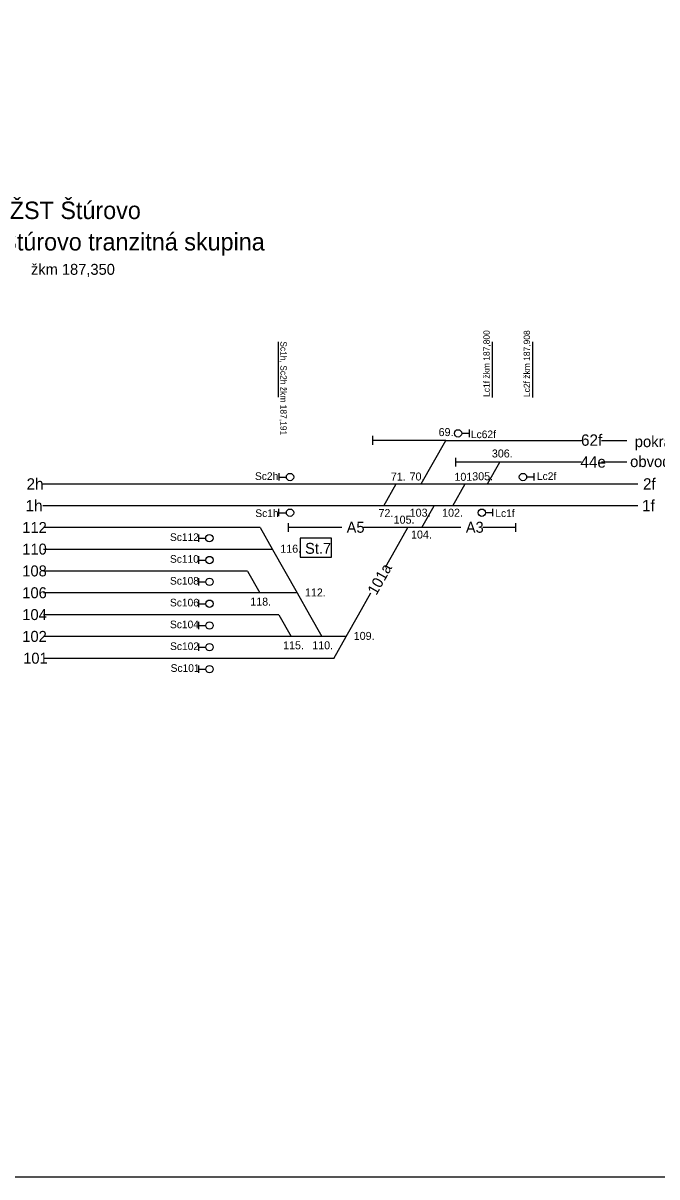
# Model space of a CAD drawing. Extents: x -119 to 851, y -238 to 59.
# Drawn here: x 499.2 to 557.3, y -238 to -132.3 of the extents above; entities that cross this region are included whole.
import ezdxf

# ---------------------------------------------------------------- set-up
doc = ezdxf.new("R2010")
doc.units = 0
for name, color, linetype in [('budova', 7, 'Continuous'), ('Level 2', 7, 'Continuous'), ('netlač', 7, 'Continuous'), ('popisky navestidla', 7, 'Continuous'), ('popisky stanic a zastavok', 7, 'Continuous'), ('PU_navestidla', 7, 'Continuous'), ('PU_oznacenie navestidiel', 7, 'Continuous'), ('PU_stan_kolaje', 7, 'Continuous'), ('PU_vlecky', 7, 'Continuous')]:
    doc.layers.add(name, color=color, linetype=linetype)

msp = doc.modelspace()

# ---------------------------------------------------------------- linework, layer by layer
at = {"layer": 'budova'}
msp.add_lwpolyline([(524.58, -181.22), (527.45, -181.22), (527.45, -179.47), (524.58, -179.47)], close=True, dxfattribs=at)
at = {"layer": 'Level 2'}
for p, q in [((531.26, -170.9), (531.26, -170.1)), ((537.94, -170.5), (531.26, -170.5)), ((538.86, -172.89), (538.86, -172.09)), ((538.96, -172.49), (538.86, -172.49)), ((543.3, -172.5), (538.9, -172.5)), ((550.36, -172.49), (542.88, -172.49)), ((554.52, -172.49), (552.2, -172.49)), ((523.53, -178.89), (523.53, -178.09)), ((528.41, -178.49), (523.53, -178.49)), ((534.45, -178.49), (530.41, -178.49)), ((539.32, -178.49), (535.73, -178.49)), ((544.36, -178.49), (541.32, -178.49)), ((544.36, -178.89), (544.36, -178.09))]:
    msp.add_line(p, q, dxfattribs=at)
at = {"layer": 'netlač'}
for p, q in [((537.94, -170.5), (550.36, -170.5)), ((552.2, -170.5), (554.52, -170.5)), ((501, -174.49), (555.55, -174.49)), ((555.55, -176.49), (501, -176.49)), ((520.94, -178.49), (501.07, -178.49)), ((535.73, -178.49), (534.45, -178.49)), ((522.07, -180.49), (501.07, -180.49)), ((519.77, -182.49), (501.07, -182.49)), ((524.33, -184.49), (501.07, -184.49)), ((522.64, -186.49), (501.07, -186.49)), ((528.8, -188.48), (501.07, -188.48)), ((527.67, -190.48), (501.07, -190.48))]:
    msp.add_line(p, q, dxfattribs=at)
at = {"layer": 'popisky navestidla'}
for p, q in [((522.62, -166.55), (522.62, -161.46)), ((542.2, -161.48), (542.2, -166.57)), ((545.88, -161.48), (545.88, -166.57))]:
    msp.add_line(p, q, dxfattribs=at)
msp.add_lwpolyline([(-118.95, -238.01), (851.05, -238.01), (851.05, 58.99), (-118.95, 58.99)], close=True, dxfattribs=at)
at = {"layer": 'PU_navestidla'}
for p, q in [((540.07, -169.86), (539.4, -169.86)), ((540.07, -169.52), (540.07, -170.2)), ((522.65, -173.52), (522.65, -174.19)), ((522.65, -173.86), (523.32, -173.86)), ((546.02, -173.86), (545.34, -173.86)), ((546.02, -173.52), (546.02, -174.19)), ((522.65, -177.46), (522.65, -176.79)), ((522.65, -177.13), (523.32, -177.13)), ((542.24, -177.13), (541.57, -177.13)), ((542.24, -177.46), (542.24, -176.79)), ((515.26, -179.14), (515.26, -179.81)), ((515.26, -179.47), (515.93, -179.47)), ((515.27, -181.13), (515.27, -181.81)), ((515.27, -181.47), (515.94, -181.47)), ((515.27, -183.13), (515.27, -183.8)), ((515.27, -183.47), (515.94, -183.47)), ((515.27, -185.13), (515.27, -185.8)), ((515.27, -185.47), (515.94, -185.47)), ((515.27, -187.13), (515.27, -187.8)), ((515.27, -187.47), (515.94, -187.47)), ((515.27, -189.13), (515.27, -189.8)), ((515.27, -189.47), (515.94, -189.47)), ((515.27, -191.13), (515.27, -191.8)), ((515.27, -191.47), (515.94, -191.47))]:
    msp.add_line(p, q, dxfattribs=at)
for centre in [(539.06, -169.86), (523.66, -173.86), (545.01, -173.86), (523.66, -177.13), (541.24, -177.13), (516.27, -179.47), (516.28, -181.47), (516.28, -183.47), (516.28, -185.47), (516.28, -187.47), (516.28, -189.46), (516.28, -191.47)]:
    msp.add_circle(centre, 0.336, dxfattribs=at)
at = {"layer": 'PU_stan_kolaje'}
for points in [[(536.81, -172.5), (537.94, -170.5)], [(535.68, -174.49), (536.81, -172.5)], [(541.75, -174.49), (542.88, -172.5)], [(532.26, -176.49), (533.39, -174.49)], [(538.58, -176.49), (539.71, -174.49)], [(535.73, -178.49), (536.86, -176.49)], [(520.94, -178.49), (522.07, -180.49)], [(533.32, -180.49), (534.45, -178.49)], [(522.07, -180.49), (523.2, -182.49)], [(532.4, -182.12), (533.32, -180.49)], [(519.77, -182.49), (520.9, -184.49)], [(523.2, -182.49), (524.33, -184.49)], [(524.33, -184.49), (525.46, -186.49)], [(529.93, -186.49), (531.06, -184.49)], [(522.64, -186.49), (523.77, -188.48)], [(525.46, -186.49), (526.59, -188.48)], [(528.8, -188.48), (529.93, -186.49)], [(527.67, -190.48), (528.8, -188.48)]]:
    msp.add_lwpolyline(points, dxfattribs=at)

# ---------------------------------------------------------------- texts
at = {"layer": 'budova'}
msp.add_text('St.7', height=1.004, dxfattribs=at).set_placement((525.04, -180.9))
at = {"layer": 'Level 2'}
for s, height, p in [('69.', 0.733, (537.28, -170.11)), ('62f', 1.044, (550.33, -171)), ('306.', 0.733, (542.16, -172.07)), ('44e', 1.044, (550.28, -173)), ('70.', 0.733, (534.62, -174.18)), ('305.', 0.733, (540.36, -174.16)), ('2h', 1.044, (499.52, -175.02)), ('71.', 0.733, (532.9, -174.19)), ('101.', 0.733, (538.73, -174.21)), ('2f', 1.044, (556.01, -175.02)), ('1h', 1.044, (499.43, -177.01)), ('1f', 1.044, (555.92, -177.01)), ('72.', 0.733, (531.77, -177.53)), ('105.', 0.733, (533.16, -178.14)), ('103.', 0.733, (534.63, -177.5)), ('102.', 0.733, (537.6, -177.5)), ('112', 1.004, (499.13, -178.99)), ('A5', 1.004, (528.85, -178.97)), ('A3', 1.004, (539.77, -178.97)), ('104.', 0.733, (534.75, -179.5)), ('110', 1.004, (499.13, -180.97)), ('116.', 0.733, (522.77, -180.8)), ('108', 1.004, (499.13, -182.97)), ('106', 1.004, (499.13, -184.97)), ('118.', 0.733, (520.02, -185.65)), ('112.', 0.733, (525.03, -184.81)), ('104', 1.004, (499.13, -186.97)), ('102', 1.004, (499.13, -188.97)), ('109.', 0.733, (529.5, -188.79)), ('115.', 0.733, (523.03, -189.65)), ('110.', 0.733, (525.7, -189.65)), ('101', 1.004, (499.21, -190.97))]:
    msp.add_text(s, height=height, dxfattribs=at).set_placement(p)
msp.add_text('101a', height=1.004, rotation=60.5159, dxfattribs=at).set_placement((531.57, -184.76))
at = {"layer": 'popisky navestidla'}
for s, rotation, p in [('Lc1f žkm 187,800', 90, (541.96, -166.52)), ('Lc2f žkm 187,908', 90, (545.65, -166.53)), ('Sc1h, Sc2h žkm 187,191', 270, (522.78, -161.42))]:
    msp.add_text(s, height=0.5793, rotation=rotation, dxfattribs=at).set_placement(p)
at = {"layer": 'popisky stanic a zastavok'}
for s, height, p in [('ŽST Štúrovo', 1.6, (497.98, -150.22)), ('obvod - Štúrovo tranzitná skupina', 1.6, (489.47, -153.1)), ('žkm 187,350', 1.0044, (499.92, -155.33))]:
    msp.add_text(s, height=height, dxfattribs=at).set_placement(p)
at = {"layer": 'PU_oznacenie navestidiel'}
for s, p in [('Lc62f', (540.24, -170.3)), ('Sc2h', (520.45, -174.13)), ('Lc2f', (546.29, -174.13)), ('Sc1h', (520.48, -177.53)), ('Lc1f', (542.48, -177.53)), ('Sc112', (512.66, -179.72)), ('Sc110', (512.66, -181.72)), ('Sc108', (512.66, -183.72)), ('Sc106', (512.66, -185.72)), ('Sc104', (512.66, -187.72)), ('Sc102', (512.67, -189.72)), ('Sc101', (512.72, -191.72))]:
    msp.add_text(s, height=0.7, dxfattribs=at).set_placement(p)
at = {"layer": 'PU_vlecky'}
for s, p in [('pokračovanie obvodu Štúrovo ', (555.25, -171.12)), ('obvodu zriaďovacieho koľajiska', (554.83, -172.95))]:
    msp.add_text(s, height=1.015, dxfattribs=at).set_placement(p)

doc.saveas('drawing.dxf')
